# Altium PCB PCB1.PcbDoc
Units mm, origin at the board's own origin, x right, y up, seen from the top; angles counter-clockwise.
Board outline 143.75 x 76.68 mm, 2 copper layers (Top Layer, Bottom Layer); 10 components, 12 nets, 220 pads, 13 vias.
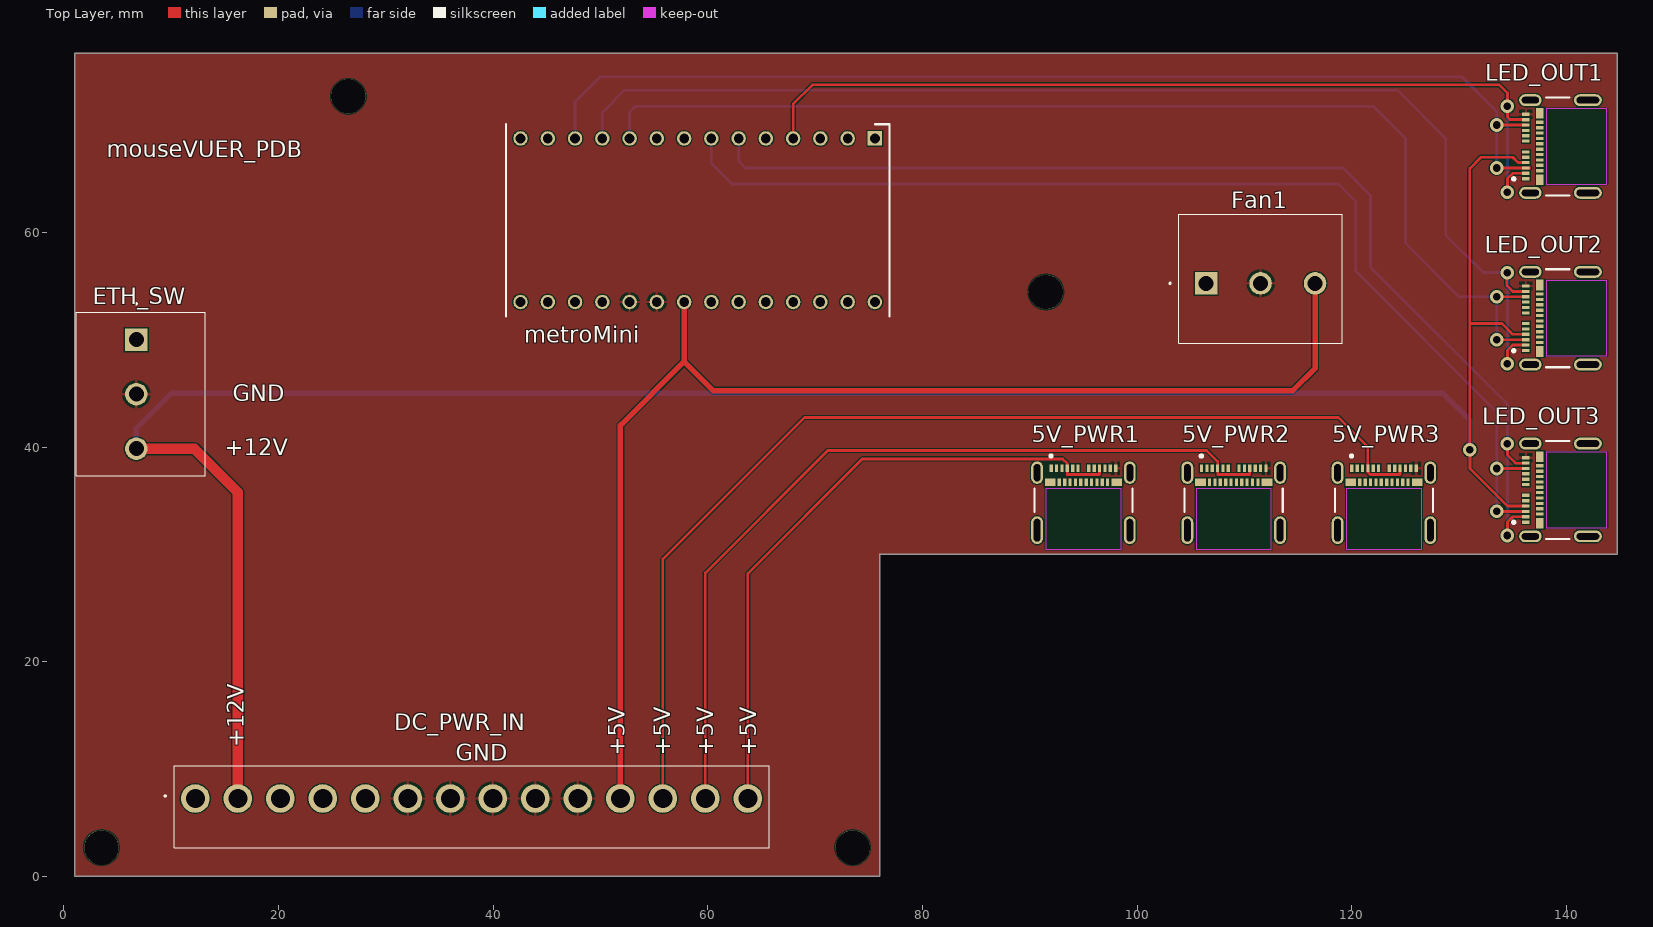
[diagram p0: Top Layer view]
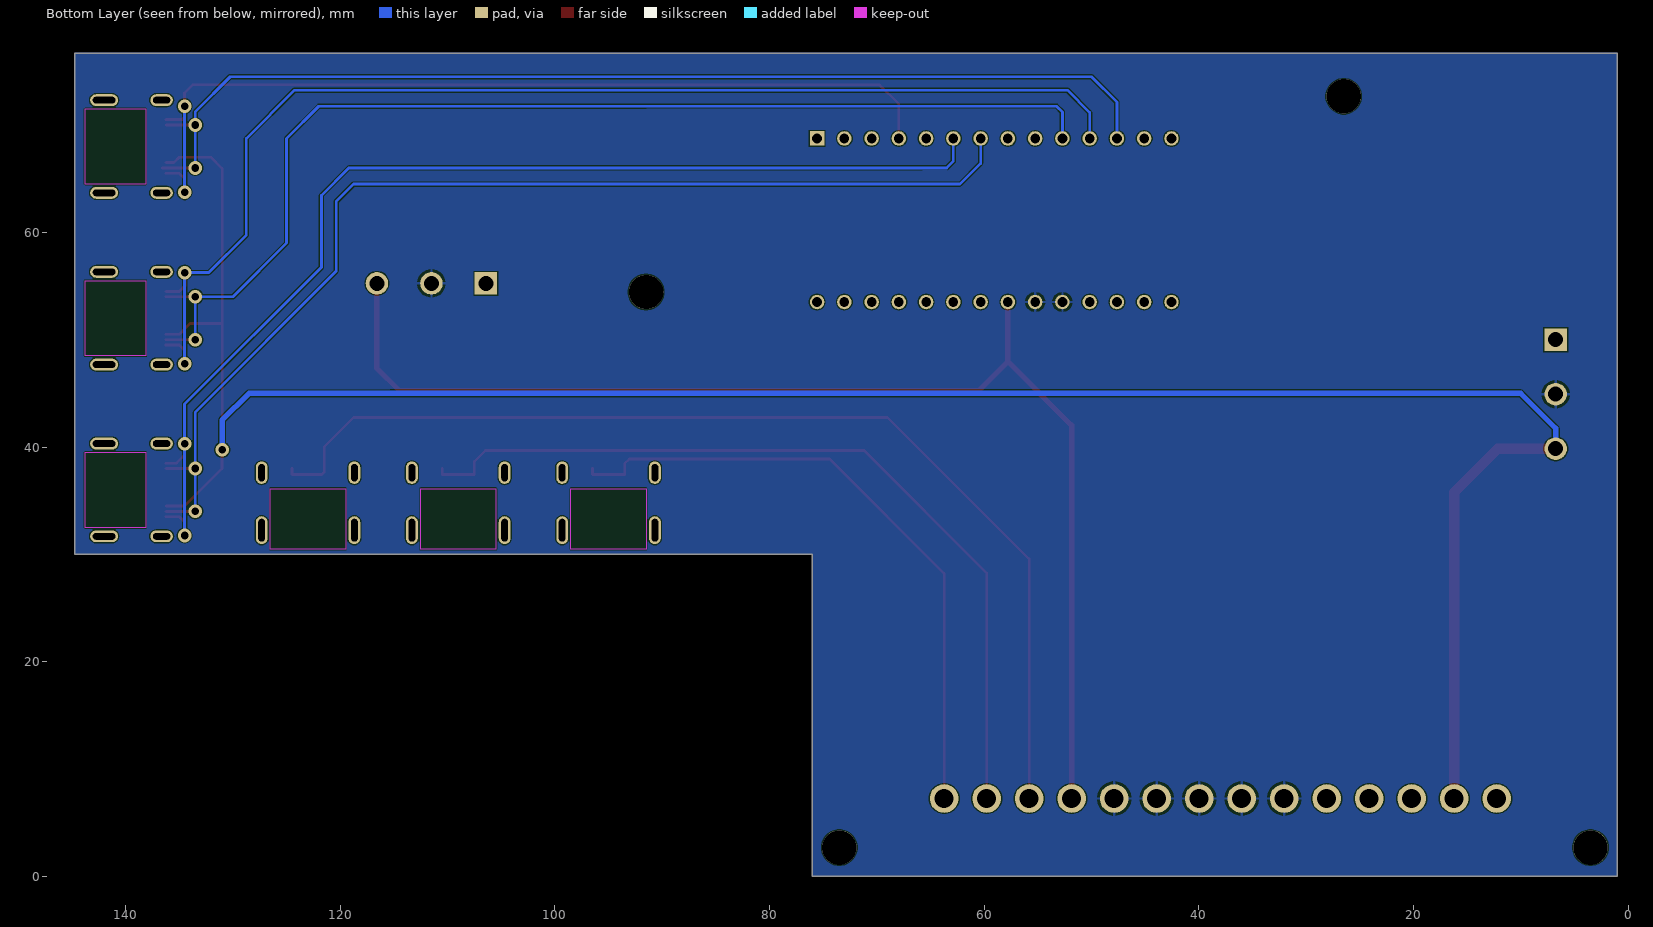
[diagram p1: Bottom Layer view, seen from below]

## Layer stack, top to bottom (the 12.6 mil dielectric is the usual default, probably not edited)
Top Solder: solder mask 0.0102, Solder Resist, Dk 3.5
Top Layer: signal copper 0.0356
Dielectric 1: dielectric 0.32, FR-4, Dk 4.8
Bottom Layer: signal copper 0.0356
Bottom Solder: solder mask 0.0102, Solder Resist, Dk 3.5

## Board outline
144.75,30 144.75,76.676 1,76.676 1,0 76,0 76,30

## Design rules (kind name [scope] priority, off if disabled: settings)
Clearance [All] p1: gap=0.1 ignorepadtopadclearanceinfootprint=FALSE
PolygonConnect [All] p1: connectstyle=Relief reliefconductorwidth=0.254 reliefentries=4 polygonreliefangle="90 Angle" airgapwidth=0.254
RoutingVias [All] p1: holewidth=0.711 width=1.27 viastyle="Through Hole" minholewidth=0.711 minwidth=1.27 maxholewidth=0.711 maxwidth=1.27
SolderMaskExpansion [All] p1: expansion=0.102 istentingtop=FALSE
Width [All] p1: maxlimit=1.27 minlimit=0.254 preferedwidth=0.254
30 further rules are at their usual default settings.

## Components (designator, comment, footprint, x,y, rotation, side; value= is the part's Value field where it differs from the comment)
5V_PWR1 "1054500101" FP-1054500101-MFG 95,34.25 r0 top
5V_PWR2 "1054500101" FP-1054500101-MFG 109,34.25 r0 top
5V_PWR3 "1054500101" FP-1054500101-MFG 123,34.25 r0 top
DC_PWR_IN "1-644753-4" 16447534 12.25,7.25 r180 top
ETH_SW "1758021" 1758021 6.75,50 r270 top
Fan1 "1758021" 1758021 106.42,55.25 r0 top
LED_OUT1 "1054500101" FP-1054500101-MFG 140,68 r90 top
LED_OUT2 "1054500101" FP-1054500101-MFG 140,52 r90 top
LED_OUT3 "1054500101" FP-1054500101-MFG 140,36 r90 top
metroMini "1-2199299-2" DIPS1524W70P254L3556H530Q28N 75.57,68.75 r270 top

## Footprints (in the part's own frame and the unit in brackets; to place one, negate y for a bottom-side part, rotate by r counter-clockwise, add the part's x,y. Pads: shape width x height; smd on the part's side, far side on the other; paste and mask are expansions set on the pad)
1758021 [mm]
  rect 2.1x2.1 / inner round 2.1 / far side rect 2.1x2.1 hole 1.4: 1(0,0)
  round 2.1 hole 1.4: 2(5.08,0) 3(10.16,0)
  silkscreen extent -3.4,-5.59 12.7,6.42, body extent -10,-3.38 10,3.38, height 5.8
16447534 [mm]
  round 2.67 hole 1.78: 1(0,0) 2(-3.96,0) 3(-7.92,0) 4(-11.88,0) 5(-15.84,0) 6(-19.8,0) 7(-23.76,0) 8(-27.72,0) 9(-31.68,0) 10(-35.64,0) 11(-39.6,0) 12(-43.56,0) 13(-47.52,0) 14(-51.48,0)
  silkscreen extent -53.47,-3.05 2.86,4.57, body extent -10,-3.38 10,3.38, height 5.8
DIPS1524W70P254L3556H530Q28N [mm]
  rect 1.35x1.35 / inner round 1.35 / far side rect 1.35x1.35 hole 0.9: 1(0,0)
  round 1.35 hole 0.9: 2(0,-2.54) 3(0,-5.08) 4(0,-7.62) 5(0,-10.16) 6(0,-12.7) 7(0,-15.24) 8(0,-17.78) 9(0,-20.32) 10(0,-22.86) 11(0,-25.4) 12(0,-27.94) 13(0,-30.48) 14(0,-33.02) 15(15.24,-33.02) 16(15.24,-30.48) 17(15.24,-27.94) 18(15.24,-25.4) 19(15.24,-22.86) 20(15.24,-20.32) 21(15.24,-17.78) 22(15.24,-15.24) 23(15.24,-12.7) 24(15.24,-10.16) 25(15.24,-7.62) 26(15.24,-5.08) 27(15.24,-2.54) 28(15.24,0)
  silkscreen extent -1.33,-34.39 16.57,1.37, body extent -1.23,-38.99 16.47,3.81, height 9.58
FP-1054500101-MFG [mm]
  rrect100% 1.1x2.1 hole 1.6 slot 0.6 at 0 deg paste-2539.97 mask+0: 1(-4.32,3.36) 2(4.32,3.36)
  rrect100% 1.1x2.6 hole 2.1 slot 0.6 at 0 deg paste-2539.97 mask+0: 3(-4.32,-2) 4(4.32,-2)
  rect 0.3x0.7 smd paste+0 mask+0: A1(-3,3.77) A2(-2.5,3.77) A3(-2,3.77) A4(-1.5,3.77) A5(-1,3.77) A6(-0.5,3.77) A7(0.5,3.77) A8(1,3.77) A9(1.5,3.77) A10(2,3.77) A11(2.5,3.77) A12(3,3.77) B2(2.25,2.47) B3(1.75,2.47) B4(1.25,2.47) B5(0.75,2.47) B6(0.25,2.47) B7(-0.25,2.47) B8(-0.75,2.47) B9(-1.25,2.47) B10(-1.75,2.47) B11(-2.25,2.47)
  rect 1x0.7 smd paste+0 mask+0: B1(3.1,2.47) B12(-3.1,2.47)
  Keep-Out Layer region: -3.5,-3.77 3.5,-3.77 3.5,1.88 -3.5,1.88
  silkscreen extent -4.57,-0.3 4.57,5.03

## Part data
5V_PWR1 5V_PWR2 5V_PWR3 LED_OUT1 LED_OUT2 LED_OUT3: library part CMP-04767-000004-1, "CONN RCP USB3.1 TYPEC 24P SMD RA", Current Rating=0.25/1.25/5A, Manufacturer=Molex, Package=0, Temperature="-30°C to +85°C", Temperature Range High=+85°C, Temperature Range Low=-30°C, Voltage Rating=30V
DC_PWR_IN: "Headers & Wire Housings 14P HDR RN STR F/L", Manufacturer_Name="TE Connectivity", Mouser Part Number=571-1-644753-4
ETH_SW Fan1: "PCB header, nominal cross section: 2.5 mm?, color: green, nominal current: 12 A, rated voltage (III/2): 320 V, contact surface: Tin, type of contact: Male connector, Number of potentials: 3, Number of rows: 1, Number of positions per row: 3, number of connections: 3, product range: MSTBV 2,5/..-G, pitch: 5.08 mm, mounting: Wave soldering, pin layout: Linear pinning, solder pin [P]: 3.9 mm, Stecksystem: CLASSIC COMBICON, Locking: without, type of packaging: packed in cardboard", Manufacturer_Name="Phoenix Contact", Mouser Part Number=651-1758021
metroMini: "TE CONNECTIVITY - 1-2199299-2 - IC SOCKET, DIP, 28POS, TH", Manufacturer_Name="TE Connectivity", Mouser Part Number=571-1-2199299-2

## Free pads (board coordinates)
  round 3.2 hole 3.2: 1(3.5,2.676) 1(26.5,72.676) 1(73.5,2.676) 1(91.5,54.442)

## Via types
v1: diameter 1.27, hole 0.711, Top Layer to Bottom Layer, 13 vias

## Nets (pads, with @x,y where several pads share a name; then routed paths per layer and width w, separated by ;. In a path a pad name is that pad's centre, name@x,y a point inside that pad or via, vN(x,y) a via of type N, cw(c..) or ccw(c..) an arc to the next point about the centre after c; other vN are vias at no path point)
+5: DC_PWR_IN.11 Fan1.3 metroMini.21 | length 117.4
  Top Layer w0.5: DC_PWR_IN.11 51.85,42.02 57.79,47.96 ; metroMini.21 57.79,47.96 ; Fan1.3 116.58,47.33 114.5,45.25 60.5,45.25 57.79,47.96
+12: DC_PWR_IN.2 ETH_SW.3 LED_OUT1.A4 LED_OUT2.A4 LED_OUT3.A4 | length 217.1
  Top Layer w0.254: LED_OUT3.A4 134.5,34.5 131.016,37.984 131.016,39.734 v1(131,39.75) 131,51.5 ; LED_OUT2.A4 135,50.5 134,51.5 131,51.5 ; LED_OUT1.A4 135.5,66.5 135,67 132.037,67 131,65.963 131,51.5
  Top Layer w1: ETH_SW.3 12.16,39.84 16.21,35.79 DC_PWR_IN.2
  Bottom Layer w0.5: ETH_SW.3 6.75,41.75 10.01,45.01 115.347,45.01 115.357,44.999 128.501,44.999 131,42.5 v1(131,39.75)
GND: 5V_PWR1.A12 5V_PWR2.A12 5V_PWR3.A12 DC_PWR_IN.6 DC_PWR_IN.7 DC_PWR_IN.8 DC_PWR_IN.9 DC_PWR_IN.10 ETH_SW.2 Fan1.2 LED_OUT1.A12 LED_OUT2.A12 LED_OUT3.A12 metroMini.19 metroMini.20
Net5V_PWR1_A4: 5V_PWR1.A4 5V_PWR1.A9 DC_PWR_IN.14 | length 59.9
  Top Layer w0.254: DC_PWR_IN.14 63.73,28.23 74.387,38.887 93.066,38.887 93.5,38.453 5V_PWR1.A4 93.5,37.44 96.5,37.44 5V_PWR1.A9
Net5V_PWR2_A4: 5V_PWR2.A4 5V_PWR2.A9 DC_PWR_IN.13 | length 78.7
  Top Layer w0.254: DC_PWR_IN.13 59.77,28.27 71.175,39.675 106.477,39.675 107.5,38.652 5V_PWR2.A4 107.5,37.44 110.5,37.44 5V_PWR2.A9
Net5V_PWR3_A4: 5V_PWR3.A4 5V_PWR3.A9 DC_PWR_IN.12 | length 100.6
  Top Layer w0.254: DC_PWR_IN.12 55.81,29.56 69,42.75 118.75,42.75 121.5,40 5V_PWR3.A4 121.5,37.656 121.717,37.44 124.5,37.44 5V_PWR3.A9
NetLED_OUT1_A2: LED_OUT1.A2 LED_OUT1.A11 metroMini.4 | length 86.6
  Top Layer w0.254: metroMini.4 67.95,71.95 69.75,73.75 133.75,73.75 134.5,73 v1(134.5,71.75) 134.5,70.75 134.727,70.523 136.207,70.523 LED_OUT1.A11 ; v1@134.306,63.944 v1(134.5,63.75) 134.5,65 135,65.5 LED_OUT1.A2
  Bottom Layer w0.254: v1(134.5,63.75) v1(134.5,71.75) v1@134.694,71.556
NetLED_OUT1_A3: LED_OUT1.A3 LED_OUT1.A10 metroMini.12 | length 102.6
  Top Layer w0.254: v1(133.5,66) LED_OUT1.A3 136.587,66 ; v1(133.5,70) LED_OUT1.A10
  Bottom Layer w0.254: metroMini.12 47.63,72.13 50,74.5 130.25,74.5 133.5,71.25 v1(133.5,70) v1(133.5,66)
NetLED_OUT2_A2: LED_OUT2.A2 LED_OUT2.A11 metroMini.11 | length 114.6
  Top Layer w0.254: v1@134.444,56.056 134.444,55.056 135,54.5 LED_OUT2.A11 ; v1(134.5,47.75) 134.5,49 135,49.5 LED_OUT2.A2 LED_OUT2.A2@136.25,49.5
  Bottom Layer w0.254: metroMini.11 50.17,71.17 52.25,73.25 124.25,73.25 128.75,68.75 128.75,59.75 132.25,56.25 v1(134.5,56.25) v1(134.5,47.75)
NetLED_OUT2_A3: LED_OUT2.A3 LED_OUT2.A10 metroMini.10 | length 106.3
  Top Layer w0.254: v1(133.5,50) LED_OUT2.A3 ; v1@133.554,54.421 133.554,54.196 133.75,54 LED_OUT2.A10
  Bottom Layer w0.254: metroMini.10 52.71,71.21 53.25,71.75 91.464,71.75 122,71.75 125,68.75 125,59 130,54 v1(133.5,54) v1(133.5,50)
NetLED_OUT3_A2: LED_OUT3.A2 LED_OUT3.A11 metroMini.6 | length 105.6
  Top Layer w0.254: v1(134.5,31.75) 134.5,33 135,33.5 LED_OUT3.A2 ; v1(134.5,40.294) 134.5,39.25 135.25,38.5 LED_OUT3.A11
  Bottom Layer w0.254: metroMini.6 62.87,66.63 63.5,66 65.75,66 ; 65.75,66 112.863,66 119.202,66 121.75,63.452 121.75,56.75 134.5,44 v1(134.5,40.294) v1(134.5,31.75)
NetLED_OUT3_A3: LED_OUT3.A3 LED_OUT3.A10 metroMini.7 | length 103.6
  Top Layer w0.254: v1(133.5,34) LED_OUT3.A3 ; v1(133.5,38) LED_OUT3.A10
  Bottom Layer w0.254: metroMini.7 60.33,66.42 62.25,64.5 118.75,64.5 120.376,62.874 120.376,56.374 133.5,43.25 v1(133.5,38) v1(133.5,34)
pads on no net: 5V_PWR1.1 5V_PWR1.2 5V_PWR1.3 5V_PWR1.4 5V_PWR1.A1 5V_PWR1.A2 5V_PWR1.A3 5V_PWR1.A5 5V_PWR1.A6 5V_PWR1.A7 5V_PWR1.A8 5V_PWR1.A10 5V_PWR1.A11 5V_PWR1.B1 5V_PWR1.B2 5V_PWR1.B3 5V_PWR1.B4 5V_PWR1.B5 5V_PWR1.B6 5V_PWR1.B7 5V_PWR1.B8 5V_PWR1.B9 5V_PWR1.B10 5V_PWR1.B11 5V_PWR1.B12 5V_PWR2.1 5V_PWR2.2 5V_PWR2.3 5V_PWR2.4 5V_PWR2.A1 5V_PWR2.A2 5V_PWR2.A3 5V_PWR2.A5 5V_PWR2.A6 5V_PWR2.A7 5V_PWR2.A8 5V_PWR2.A10 5V_PWR2.A11 5V_PWR2.B1 5V_PWR2.B2 5V_PWR2.B3 5V_PWR2.B4 5V_PWR2.B5 5V_PWR2.B6 5V_PWR2.B7 5V_PWR2.B8 5V_PWR2.B9 5V_PWR2.B10 5V_PWR2.B11 5V_PWR2.B12 5V_PWR3.1 5V_PWR3.2 5V_PWR3.3 5V_PWR3.4 5V_PWR3.A1 5V_PWR3.A2 5V_PWR3.A3 5V_PWR3.A5 5V_PWR3.A6 5V_PWR3.A7 5V_PWR3.A8 5V_PWR3.A10 5V_PWR3.A11 5V_PWR3.B1 5V_PWR3.B2 5V_PWR3.B3 5V_PWR3.B4 5V_PWR3.B5 5V_PWR3.B6 5V_PWR3.B7 5V_PWR3.B8 5V_PWR3.B9 5V_PWR3.B10 5V_PWR3.B11 5V_PWR3.B12 DC_PWR_IN.1 DC_PWR_IN.3 DC_PWR_IN.4 DC_PWR_IN.5 ETH_SW.1 Fan1.1 LED_OUT1.1 LED_OUT1.2 LED_OUT1.3 LED_OUT1.4 LED_OUT1.A1 LED_OUT1.A5 LED_OUT1.A6 LED_OUT1.A7 LED_OUT1.A8 LED_OUT1.A9 LED_OUT1.B1 LED_OUT1.B2 LED_OUT1.B3 LED_OUT1.B4 LED_OUT1.B5 LED_OUT1.B6 LED_OUT1.B7 LED_OUT1.B8 LED_OUT1.B9 LED_OUT1.B10 LED_OUT1.B11 LED_OUT1.B12 LED_OUT2.1 LED_OUT2.2 LED_OUT2.3 LED_OUT2.4 LED_OUT2.A1 LED_OUT2.A5 LED_OUT2.A6 LED_OUT2.A7 LED_OUT2.A8 LED_OUT2.A9 LED_OUT2.B1 LED_OUT2.B2 LED_OUT2.B3 LED_OUT2.B4 LED_OUT2.B5 LED_OUT2.B6 LED_OUT2.B7 LED_OUT2.B8 LED_OUT2.B9 LED_OUT2.B10 LED_OUT2.B11 LED_OUT2.B12 LED_OUT3.1 LED_OUT3.2 LED_OUT3.3 LED_OUT3.4 LED_OUT3.A1 LED_OUT3.A5 LED_OUT3.A6 LED_OUT3.A7 LED_OUT3.A8 LED_OUT3.A9 LED_OUT3.B1 LED_OUT3.B2 LED_OUT3.B3 LED_OUT3.B4 LED_OUT3.B5 LED_OUT3.B6 LED_OUT3.B7 LED_OUT3.B8 LED_OUT3.B9 LED_OUT3.B10 LED_OUT3.B11 LED_OUT3.B12 metroMini.1 metroMini.2 metroMini.3 metroMini.5 metroMini.8 metroMini.9 metroMini.13 metroMini.14 metroMini.15 metroMini.16 metroMini.17 metroMini.18 metroMini.22 metroMini.23 metroMini.24 metroMini.25 metroMini.26 metroMini.27 metroMini.28

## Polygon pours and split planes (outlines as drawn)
GND on Bottom Layer "GND_L02_P000" (solid, pour order 0): 1,0 1,76.75 144.75,76.75 144.75,30 76,30 76,0
GND on Top Layer "GND_L01_P001" (solid, pour order 1): 1,0 1,76.75 144.75,76.75 144.75,30 76,30 76,0

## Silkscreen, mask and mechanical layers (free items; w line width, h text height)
Top Overlay:
  text "mouseVUER_PDB" at 4.004,67.008 h1.52
  text "GND" at 15.754,44.254 h1.52
  text "+12V" at 15.004,39.254 h1.52
  text "+12V" at 16.746,12.004 h1.52 r90
  text "+5V" at 52.246,11.254 h1.52 r90
  text "+5V" at 56.496,11.254 h1.52 r90
  text "+5V" at 60.496,11.254 h1.52 r90
  text "+5V" at 64.496,11.254 h1.52 r90
  text "GND" at 36.504,10.754 h1.52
